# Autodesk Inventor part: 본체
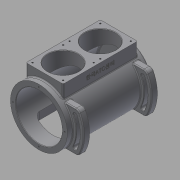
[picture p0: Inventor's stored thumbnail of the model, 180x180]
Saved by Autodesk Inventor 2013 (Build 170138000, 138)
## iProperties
Created: 2016-11
Part Number: 본체
Material: 알루미늄 6061
Document SubType Name: Modeling
Designer: mduedu
Density: 2.71 g/cm^3
Author: mduedu
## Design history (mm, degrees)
sketch "스케치1"
  geometry: C1 r 65 at (0, 0); 1 further point
  constraints: 1 centre point, 1 coincident
  dimensions: "d119" = 130 diameter of C1
extrude "돌출1" new body sketch "스케치1" distance "d3" = 98; taper "d4" = 0 deg; dims "d132" = 97, "d133" = 0
feature "쉘1" dims "d120" = 12, "d134" = 8
node "작업 평면2"
sketch "스케치13"
  geometry: L1 (42.5, 85)-(-42.5, 85); L2 (-42.5, 85)-(-42.5, -85); L3 (-42.5, -85)-(42.5, -85); L4 (42.5, -85)-(42.5, 85); 2 further points
  constraints: 8 end point, 2 parallel, 1 horizontal, 1 midpoint, 1 perpendicular, 1 vertical alignment
  dimensions: "d122" = 170 distance of L1.end L2.end; "d124" = 85 distance of L2.end L3.end; "d125" = 85 distance from line of point (0, 0) L1 (= 0.5 x d122)
extrude "돌출11" join sketch "스케치13" stored distance "d126" = 10; taper "d127" = 0 deg
sketch "스케치14"
  geometry: L1 (65, 97)-(-65, 97) reference; C1 r 35 at (0, 42.5); 1 further point
  constraints: 1 centre point, 1 vertical alignment
  dimensions: "d128" = 70 diameter of C1; "d129" = 54.5 distance from line of C1.centre L1
extrude "돌출12" cut sketch "스케치14" stored distance "d130" = 10; taper "d131" = 0 deg
sketch "스케치15"
  geometry: C1 r 53 at (0, 0) reference; 1 further point
extrude "돌출13" cut sketch "스케치15" stored distance "d135" = 10; taper "d136" = 0 deg
chamfer "모따기1" distance "d54" = 1; stored, may be unused: second distance "d55" = 2, angle "d56" = 45 deg
sketch "스케치8"
  geometry: C1 r 23 at (0, 0); C2 r 65 at (0, 0) reference; 1 further point
  constraints: 1 centre point, 1 concentric
  dimensions: "d57" = 46 diameter of C1
extrude "돌출8" join sketch "스케치8" distance "d58" = 14; taper "d59" = 0 deg
hole "구멍3" diameter "d62" = 24; stored, may be unused: countersink angle "d66" = 90 deg, drill point angle "d68" = 0 deg; dims "d63" = 6, "d64" = 28, "d65" = 8, "d67" = 14, "d169" = 10, "d170" = 10
fillet "모깎기11" dims "d69" = 3
fillet "모깎기12" dims "d70" = 3
fillet "모깎기13" dims "d71" = 0.3
chamfer "모따기2" distance "d72" = 1; stored, may be unused: second distance "d73" = 2, angle "d74" = 45 deg
node "작업 평면3"
sketch "스케치16"
  geometry: L1 (-42.5, -80)-(47.5, -80); L2 (-42.5, -80)-(21.14, -16.36); L3 (-42.5, -80)-(21.14, -143.64); L4 (3.462, -34.038)-(34.879, -34.038); L5 (3.462, -125.962)-(34.879, -125.962); A1 r 65 centre (-42.5, -80) between (3.462, -34.038) and (3.462, -125.962) reference; A2 r 90 centre (-42.5, -80) between (34.879, -125.962) and (34.879, -34.038); A3 r 90 centre (-42.5, -80) between (34.879, -34.038) and (34.879, -125.962); A4 r 65 centre (-42.5, -80) between (3.462, -125.962) and (3.462, -34.038); 1 further point
  constraints: 11 point on circle, 10 end point, 3 centre point, 2 parallel, 2 point on line, 1 coincident, 1 horizontal
  dimensions: "d140" = 45 deg angle of L3 L1; "d141" = 45 deg angle of L2 L1; "d142" = 25 radial gap between concentric circles of A1 A2
extrude "돌출14" join sketch "스케치16" distance "d143" = 15; taper "d144" = 0 deg
sketch "스케치17"
  geometry: L1 (-42.5, -80)-(34.414, -80); L2 (-42.5, -80)-(27.208, -47.495); L3 (-42.5, -80)-(27.208, -112.505); L4 (34.879, -34.038)-(3.462, -34.038) reference; L5 (3.462, -125.962)-(34.879, -125.962) reference; A1 r 65 centre (-42.5, -80) between (3.462, -34.038) and (3.462, -125.962) reference; A2 r 76.914 centre (-42.5, -80) between (19.17, -125.962) and (19.17, -34.038); A3 r 4 centre (27.208, -47.495) between (23.582, -49.185) and (30.833, -45.804); A4 r 4 centre (27.208, -112.505) between (30.833, -114.196) and (23.582, -110.815); A5 r 80.914 centre (-42.5, -80) between (30.833, -114.196) and (30.833, -45.804); A6 r 72.914 centre (-42.5, -80) between (23.582, -110.815) and (23.582, -49.185); 1 further point
  constraints: 13 point on circle, 6 end point, 5 centre point, 5 coincident, 3 midpoint, 2 point on line, 1 equal radius, 1 horizontal
  dimensions: "d145" = 25 deg angle of L1 L3; "d146" = 25 deg angle of L2 L1; "d147" = 8 diameter of A3
extrude "돌출15" cut sketch "스케치17" stored distance "d150" = 15; taper "d151" = 0 deg
fillet "모깎기17" dims "d152" = 10
fillet "모깎기18" dims "d153" = 2
fillet "모깎기19" dims "d154" = 2
chamfer "모따기4" distance "d155" = 1; stored, may be unused: second distance "d156" = 2, angle "d157" = 45 deg
fillet "모깎기20" dims "d159" = 3
fillet "모깎기21" dims "d160" = 3
fillet "모깎기22" dims "d161" = 3
node "작업 평면4"
sketch "스케치18"
  geometry: L1 (-42.5, 65)-(42.5, 65); L2 (42.5, 65)-(42.5, -65); L3 (42.5, -65)-(-42.5, -65); L4 (-42.5, -65)-(-42.5, 65); 2 further points
  constraints: 8 end point, 2 parallel, 1 horizontal, 1 midpoint, 1 perpendicular, 1 vertical alignment
  dimensions: "d162" = 130 distance of L1.end L2.end; "d164" = 85 distance of L2.end L3.end; "d165" = 65 distance from line of point (0, 0) L1 (= 0.5 x d162)
extrude "돌출16" cut sketch "스케치18" stored distance "d166" = 15; taper "d167" = 0 deg
fillet "모깎기23" dims "d168" = 10
fillet "모깎기24" dims "d173" = 3
sketch "스케치19"
  geometry: 4 further points
  constraints: 4 other
hole "구멍6" sketch "스케치19" at (0, -59), (59, 0), (-59, 0), (0, 59) diameter "d174" = 3.242; stored, may be unused: countersink angle "d178" = 90 deg, drill point angle "d180" = 120 deg; dims "d175" = 7, "d176" = 4, "d177" = 2, "d179" = 9
sketch "스케치20"
  geometry: L1 (35, -77.5)-(-35, -77.5); L2 (-35, -77.5)-(-35, -7.5); L3 (-35, -7.5)-(35, -7.5); L4 (35, -7.5)-(35, -77.5); L5 (35, -77.5)-(-35, -7.5); L6 (-35, -77.5)-(35, -7.5); C1 r 36 at (0, -42.5) reference; 5 further points
  constraints: 12 end point, 4 coincident, 2 midpoint, 2 parallel, 1 horizontal, 1 perpendicular
  dimensions: "d181" = 70 distance of L2.end L3.end; "d182" = 70 distance of L1.end L2.end
hole "구멍7" sketch "스케치20" at (-35, -77.5), (-35, -7.5), (35, -7.5), (35, -77.5) diameter "d183" = 3.242; stored, may be unused: countersink angle "d187" = 90 deg, drill point angle "d189" = 118 deg; dims "d184" = 7, "d185" = 4, "d186" = 2, "d188" = 9
sketch "스케치21"
  geometry: L1 (164, 0)-(0, 0) reference; L2 (-3, 0)-(-3, -24.649) reference; 3 further points
  constraints: 1 midpoint, 1 vertical alignment, 1 other
  dimensions: "d190" = 15 distance from line of point (82, -15) L1; "d191" = 85 distance from line of point (82, 0) L2 (derived)
feature "엠보싱2" sketch "스케치21" dims "d3" = 98, "d4" = 0, "d119" = 130, "d132" = 97, "d133" = 0, "d192" = 0.5, "d193" = 0
node "솔리드1"
mirror "대칭5"
mirror "대칭6"
mirror "대칭7"
